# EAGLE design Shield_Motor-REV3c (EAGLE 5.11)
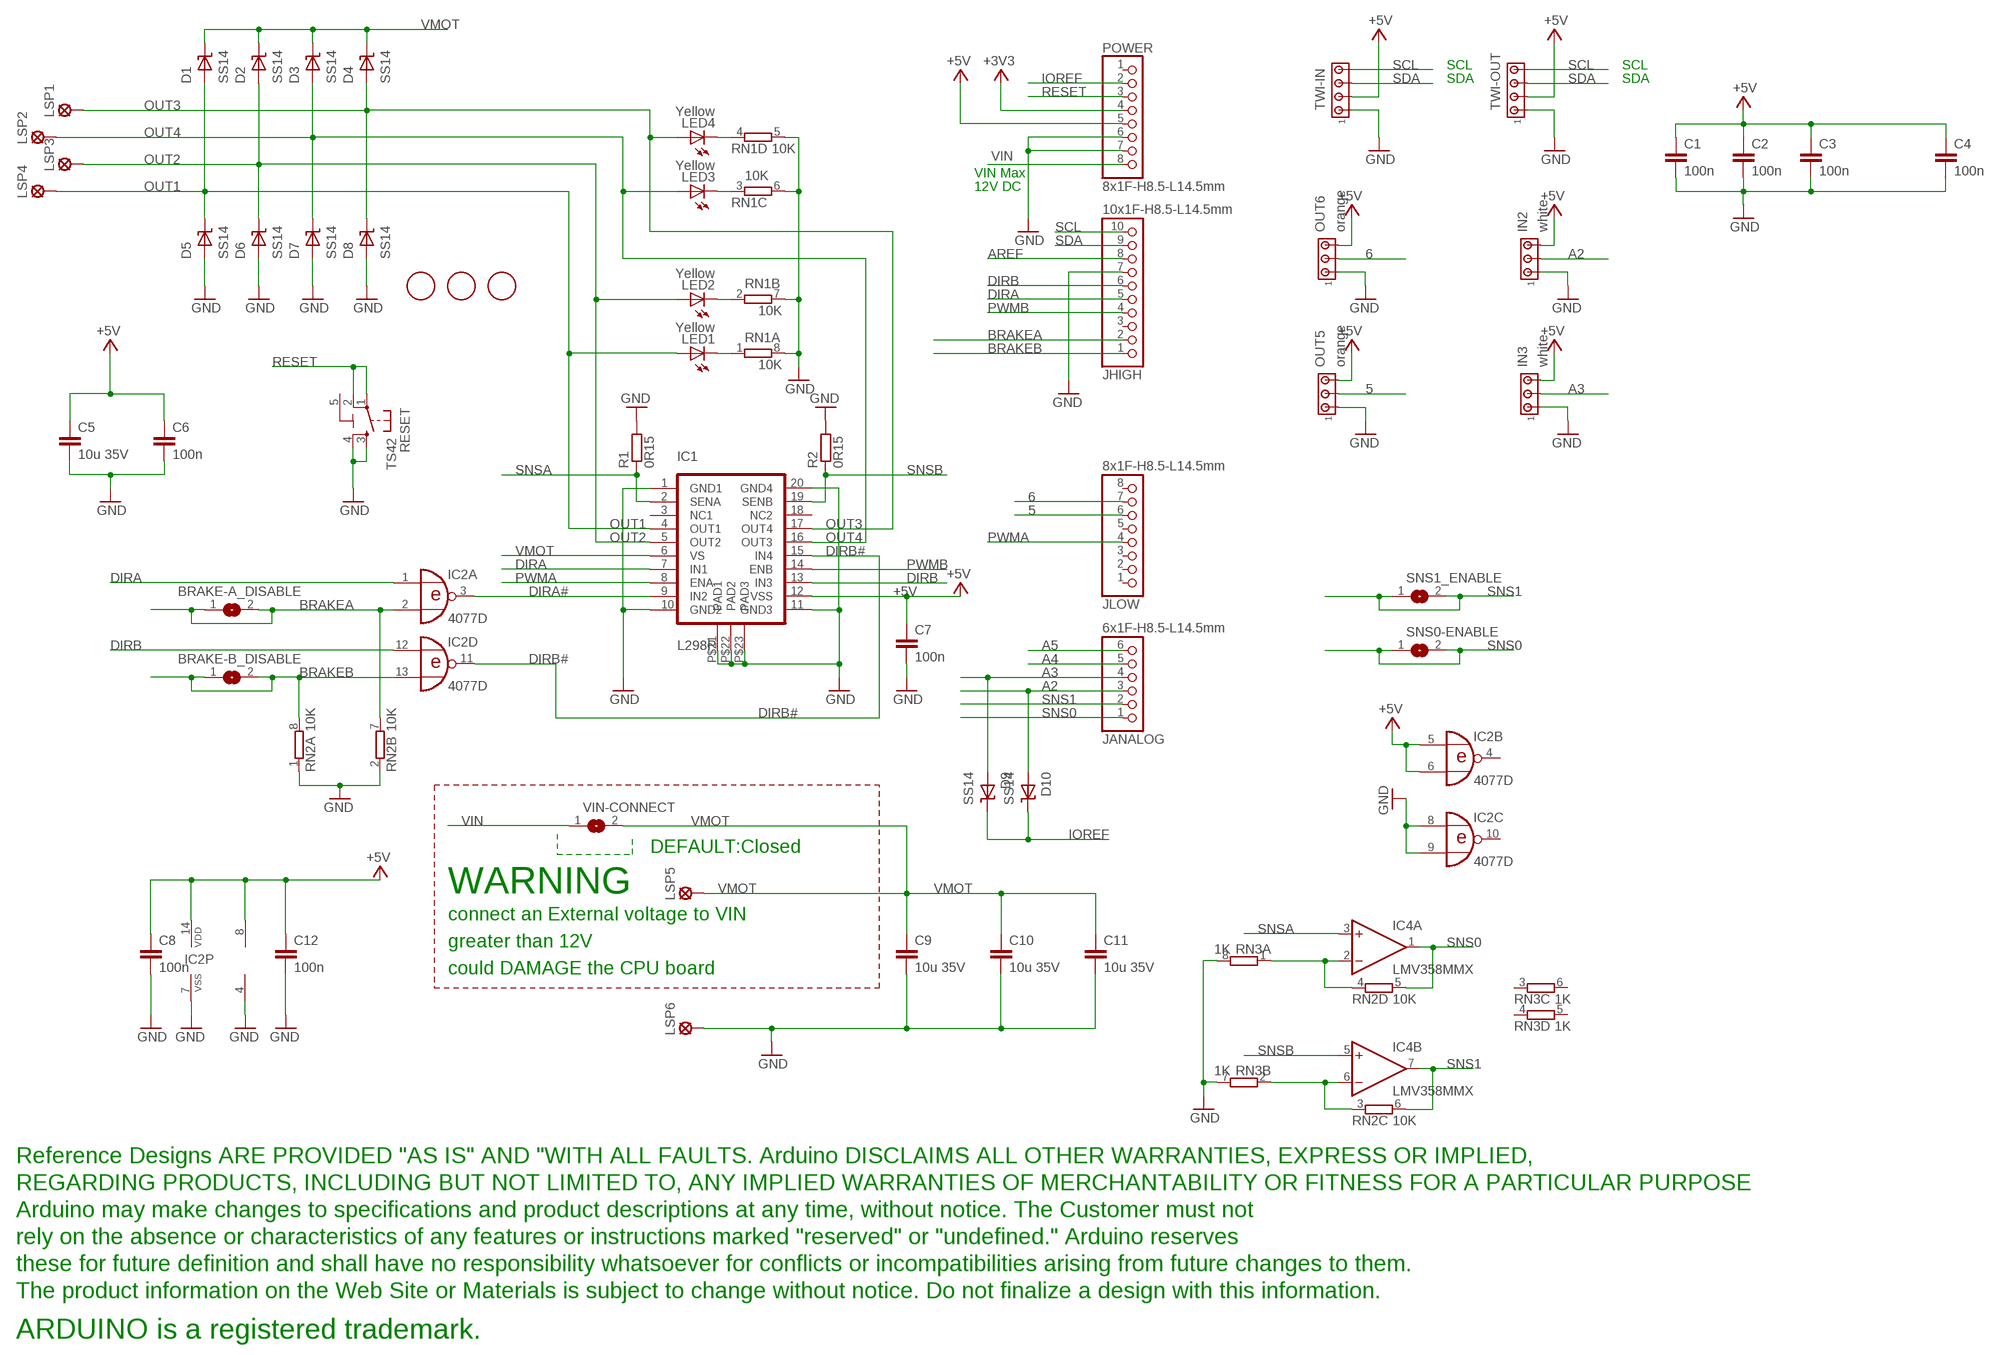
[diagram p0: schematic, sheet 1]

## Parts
BRAKE-A_DISABLE  SJ  [SJ]
BRAKE-B_DISABLE  SJ  [SJ]
C1  100n  C-EUC0603  [C0603-ROUND]
C2  100n  C-EUC0603  [C0603-ROUND]
C3  100n  C-EUC0603  [C0603-ROUND]
C4  100n  C-EUC0603  [C0603-ROUND]
C5  10u 35V  C-EUC1210  [C1210]
C6  100n  C-EUC0603  [C0603-ROUND]
C7  100n  C-EUC0603  [C0603-ROUND]
C8  100n  C-EUC0603  [C0603-ROUND]
C9  10u 35V  C-EUC1210  [C1210]
C10  10u 35V  C-EUC1210  [C1210]
C11  10u 35V  C-EUC1210  [C1210]
C12  100n  C-EUC0603  [C0603-ROUND]
D1  SS14  [SMA]
D2  SS14  [SMA]
D3  SS14  [SMA]
D4  SS14  [SMA]
D5  SS14  [SMA]
D6  SS14  [SMA]
D7  SS14  [SMA]
D8  SS14  [SMA]
D9  SS14  [SMA]
D10  SS14  [SMA]
FID1  FIDUCIALMOUNT  [FIDUCIA-MOUNT]
FID2  FIDUCIALMOUNT  [FIDUCIA-MOUNT]
FID3  FIDUCIALMOUNT  [FIDUCIA-MOUNT]
IC1  L298P  [POWER-SO20]
IC2  4077D  [SO14]
IC4  LMV358MMX  [MSOP08]
IN2  white  MTA03-100  [10X03MTA]
IN3  white  MTA03-100  [10X03MTA]
JANALOG  6x1F-H8.5-L14.5mm  PINHD-1X6TH  [1X06-TH]
JHIGH  10x1F-H8.5-L14.5mm  PINHD-1X10TH  [1X10-TH]
JLOW  8x1F-H8.5-L14.5mm  PINHD-1X8TH  [1X08-TH]
LED1  Yellow  LEDCHIPLED_0805  [CHIPLED_0805]
LED2  Yellow  LEDCHIPLED_0805  [CHIPLED_0805]
LED3  Yellow  LEDCHIPLED_0805  [CHIPLED_0805]
LED4  Yellow  LEDCHIPLED_0805  [CHIPLED_0805]
LSP1  LSP13  [LSP13]
LSP2  LSP13  [LSP13]
LSP3  LSP13  [LSP13]
LSP4  LSP13  [LSP13]
LSP5  LSP13  [LSP13]
LSP6  LSP13  [LSP13]
OUT5  orange  MTA03-100  [10X03MTA]
OUT6  orange  MTA03-100  [10X03MTA]
POWER  8x1F-H8.5-L14.5mm  PINHD-1X8TH  [1X08-TH]
R1  0R15  R-EU_R1206  [R1206]
R2  0R15  R-EU_R1206  [R1206]
RESET  TS42  [TS42]
RN1  10K  4R-NCAY16  [CAY16]
RN2  10K  4R-NCAY16  [CAY16]
RN3  1K  4R-NCAY16  [CAY16]
SNS0-ENABLE  SJ  [SJ]
SNS1_ENABLE  SJ  [SJ]
TWI-IN  MTA04-100  [10X04MTA]
TWI-OUT  MTA04-100  [10X04MTA]
U$1  DISCLAIMER  [DISCLAIMER]
VIN-CONNECT  SJ  [SJ]

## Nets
5: JLOW.6 OUT5.2
6: JLOW.7 OUT6.2
+3V3 [power]: POWER.4
+5V [power]: C1.1 C2.1 C3.1 C4.1 C5.1 C6.1 C7.1 C8.1 C12.1 IC1.P$12(VSS) IC2.5(B:I0) IC2.6(B:I1) IC2.14(P:VDD) IC4.8(P:V+) IN2.3 IN3.3 OUT5.3 OUT6.3 POWER.5 TWI-IN.2 TWI-OUT.2
A2: D10.P$2(A) IN2.2 JANALOG.3
A3: D9.P$2(A) IN3.2 JANALOG.4
A4: JANALOG.5
A5: JANALOG.6
AREF: JHIGH.8
BRAKEA: BRAKE-A_DISABLE.1 BRAKE-A_DISABLE.2 IC2.2(A:I1) JHIGH.2 RN2.7
BRAKEB: BRAKE-B_DISABLE.1 BRAKE-B_DISABLE.2 IC2.13(D:I1) JHIGH.1 RN2.8
DIRA: IC1.P$7(IN1) IC2.1(A:I0) JHIGH.5
DIRA#: IC1.P$9(IN2) IC2.3(A:O)
DIRB: IC1.P$13(IN3) IC2.12(D:I0) JHIGH.6
DIRB#: IC1.P$15(IN4) IC2.11(D:O)
GND [power]: C1.2 C2.2 C3.2 C4.2 C5.2 C6.2 C7.2 C8.2 C9.2 C10.2 C11.2 C12.2 D5.P$2(A) D6.P$2(A) D7.P$2(A) D8.P$2(A) IC1.P$1(GND1) IC1.P$10(GND2) IC1.P$11(GND3) IC1.P$20(GND4) IC1.P$21(PAD1) IC1.P$22(PAD2) IC1.P$23(PAD3) IC2.7(P:VSS) IC2.8(C:I0) IC2.9(C:I1) IC4.4(P:V-) IN2.1 IN3.1 JHIGH.7 LSP6.MP OUT5.1 OUT6.1 POWER.6 POWER.7 R1.2 R2.2 RESET.3 RESET.4 RN1.5 RN1.6 RN1.7 RN1.8 RN2.1 RN2.2 RN3.7 RN3.8 TWI-IN.1 TWI-OUT.1
IOREF: D9.P$1(K) D10.P$1(K) POWER.2
N$1: LED4.C RN1.4
N$2: LED3.C RN1.3
N$3: LED2.C RN1.2
N$4: LED1.C RN1.1
N$5: IC4.2(A:-IN) RN2.4 RN3.1
N$7: IC4.6(B:-IN) RN2.3 RN3.2
OUT1: D1.P$2(A) D5.P$1(K) IC1.P$4(OUT1) LED1.A LSP4.MP
OUT2: D2.P$2(A) D6.P$1(K) IC1.P$5(OUT2) LED2.A LSP3.MP
OUT3: D4.P$2(A) D8.P$1(K) IC1.P$17(OUT4) LED4.A LSP1.MP
OUT4: D3.P$2(A) D7.P$1(K) IC1.P$16(OUT3) LED3.A LSP2.MP
PWMA: IC1.P$8(ENA) JLOW.4
PWMB: IC1.P$14(ENB) JHIGH.4
RESET: POWER.3 RESET.1 RESET.2
SCL: JHIGH.10 TWI-IN.4 TWI-OUT.4
SDA: JHIGH.9 TWI-IN.3 TWI-OUT.3
SNS0: IC4.1(A:OUT) JANALOG.1 RN2.5 SNS0-ENABLE.1 SNS0-ENABLE.2
SNS1: IC4.7(B:OUT) JANALOG.2 RN2.6 SNS1_ENABLE.1 SNS1_ENABLE.2
SNSA: IC1.P$2(SENA) IC4.3(A:+IN) R1.1
SNSB: IC1.P$19(SENB) IC4.5(B:+IN) R2.1
VIN [VIN]: POWER.8 VIN-CONNECT.1
VMOT: C9.1 C10.1 C11.1 D1.P$1(K) D2.P$1(K) D3.P$1(K) D4.P$1(K) IC1.P$6(VS) LSP5.MP VIN-CONNECT.2
Unconnected: IC1.P$3(NC1) IC1.P$18(NC2) IC2.4(B:O) IC2.10(C:O) JHIGH.3 JLOW.1 JLOW.2 JLOW.3 JLOW.5 JLOW.8 POWER.1 RN3.3 RN3.4 RN3.5 RN3.6

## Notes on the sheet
- SCL | SCL
- SDA | SDA
- VIN Max
- 12V DC
- DEFAULT:Closed
- WARNING
- connect an External voltage to VIN
- greater than 12V
- could DAMAGE the CPU board

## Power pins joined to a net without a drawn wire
5-GND: RESET.5(5-GND)

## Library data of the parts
BRAKE-A_DISABLE BRAKE-B_DISABLE SNS0-ENABLE SNS1_ENABLE VIN-CONNECT = jumper:SJ: SMD solder JUMPER
C1-C12 = SmartPrj:C-EU: CAPACITOR, European symbol
D1-D10 = SmartPrj:SS14: DIODE SS14 Diode Schottky 1A 40v
FID1-FID3 = SmartPrj:FIDUCIALMOUNT
IC1 = SmartPrj:L298P: L298P DUAL FUL-BRIDGE DRIVER PowerSO20
IC2 = 40xx:4077: Quad XNOR
IC4 = linear:LMV358?*: Dual General Purpose, Low Voltage, Rail-to-Rail Output Operational Amplifiers Source: http://www.national.com/mpf/LM/LMV321.html http://www.national.com/dt/lmv_qual.pdf
IN2 IN3 OUT5 OUT6 = SmartPrj:MTA03-100: PIN HEADER; OC_FARNELL: unknown; OC_NEWARK: unknown
JANALOG = SmartPrj:PINHD-1X6: PIN HEADER
JHIGH = SmartPrj:PINHD-1X10: PIN HEADER
JLOW POWER = SmartPrj:PINHD-1X8: PIN HEADER
LED1-LED4 = led:LED: LED
LSP1-LSP6 = solpad:LSP13: SOLDER PAD
R1 R2 = SmartPrj:R-EU_: RESISTOR, European symbol
RESET = SmartPrj:TS42: TS42 Dongnan Electronics Tact switch VDC 12V - 50mA
RN1-RN3 = resistor-dil:4R-N: Array Chip Resistor Source: RS Component / Phycomp
TWI-IN TWI-OUT = con-amp:MTA04-100: AMP connector
U$1 = SmartPrj:DISCLAIMER

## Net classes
0 default: width 0.406 mm, drill 0.61 mm, clearance 0.152 mm
1 power: width 0.406 mm, drill 0.61 mm, clearance 0.152 mm
2 VIN: width 0.406 mm, drill 0.61 mm, clearance 0.152 mm

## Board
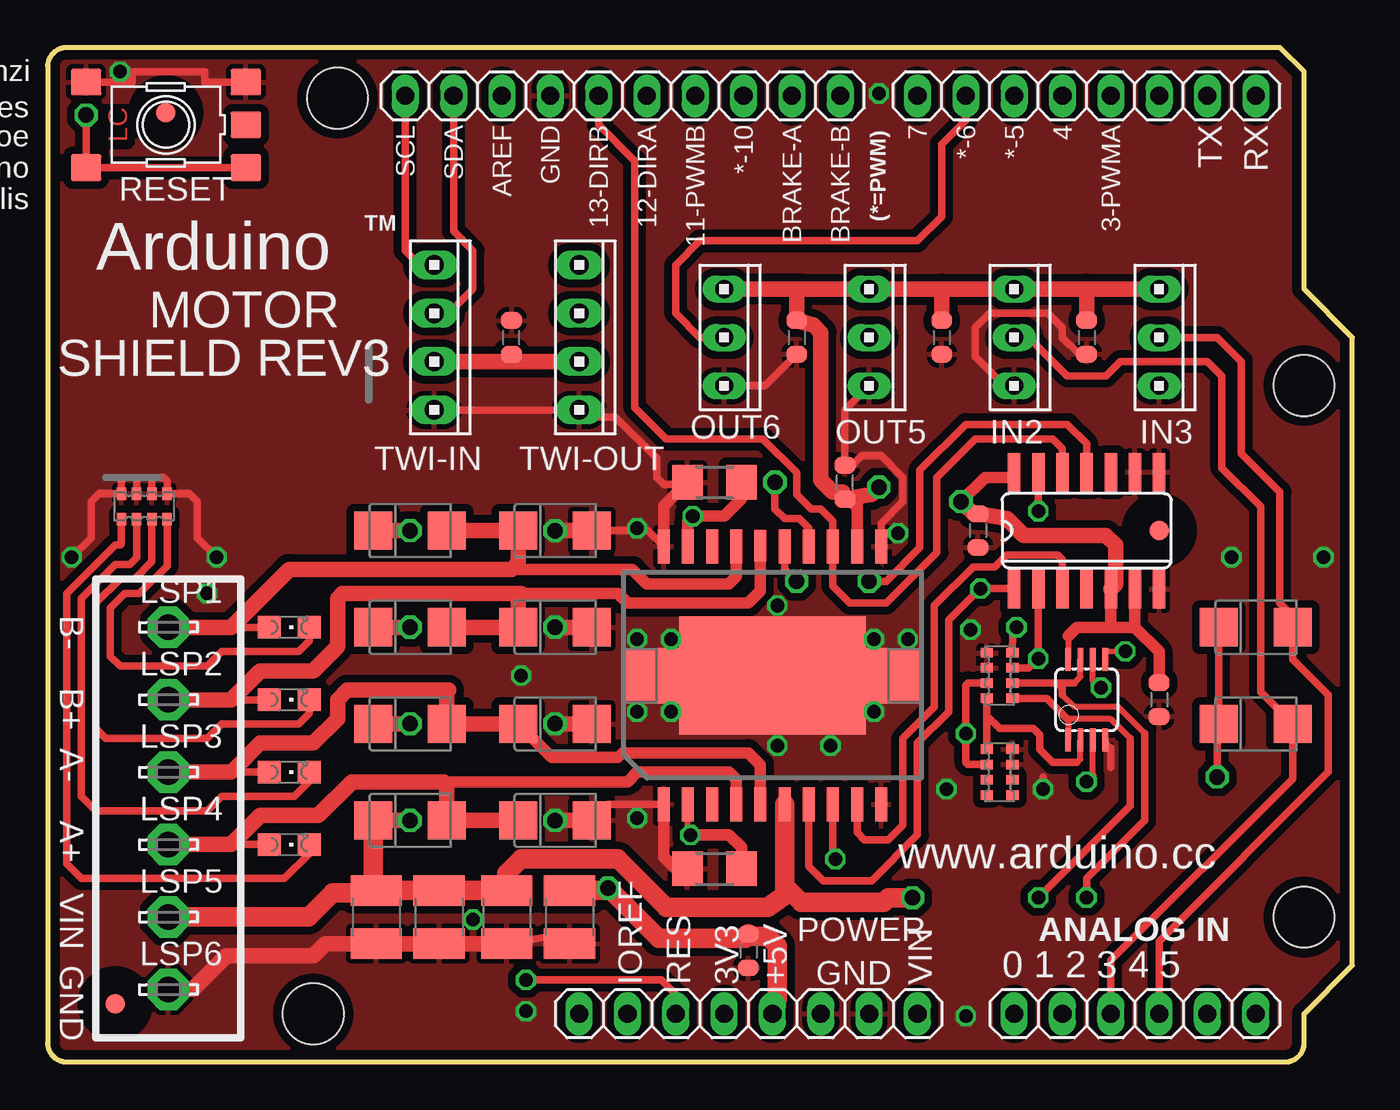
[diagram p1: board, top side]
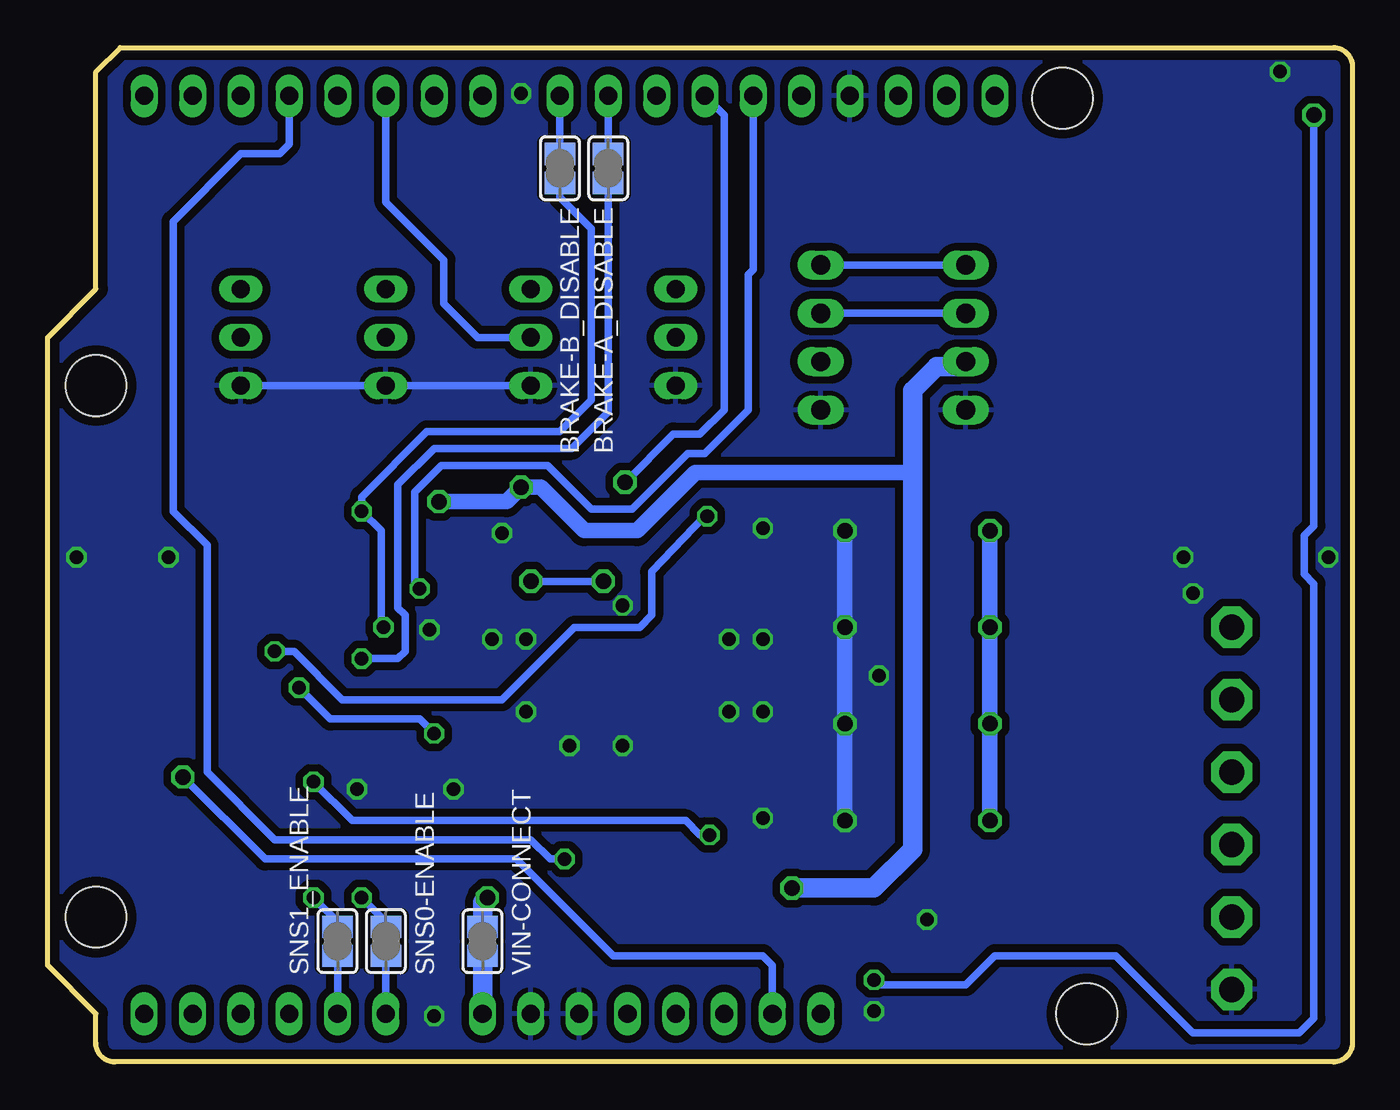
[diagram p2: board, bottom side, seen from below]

Size 68.58 x 53.34 mm. Coordinates in mm from the lower left corner, seen from the top.
Outline: 66.04,2.54 68.58,5.08 68.58,38.1 66.04,40.64 66.04,52.07 64.77,53.34 1,53.34 arc90 0,52.34 0,1 arc90 1,0 65.04,0 arc90 66.04,1 66.04,2.54
Copper layers (1*16): Top 0.035mm / dielectric 1.5mm / Bottom 0.035mm
Design rules "default *": minimum track width 10mil, minimum drill 10mil, track to track 12mil, track to pad 12mil, pad to pad 12mil, via to via 12mil, smd to smd 12mil, copper to edge 20mil, drill to drill 10mil, minimum pad ring 6mil, minimum via ring 6mil, stop-mask expansion 2mil, vias tented up to drill 32mil, thermal gap 10mil
Holes 3.2 mm at 66.04,35.56 66.04,7.62 15.24,50.67 13.97,2.54

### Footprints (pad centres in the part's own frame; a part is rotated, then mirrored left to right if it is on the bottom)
SJ = smd 1.168 x 1.6: 1 -0.762,0; 2 0.762,0
C0603-ROUND = smd 0.898 x 1.1: 1 -0.889,0; 2 0.889,0
C1210 = smd 1.6 x 2.7: 1 -1.4,0; 2 1.4,0
SMA = smd 2 x 2: P$1 -1.94,0; P$2 1.94,0
FIDUCIA-MOUNT = smd 1.016 x 1.016: P$1 0,0
POWER-SO20 = smd 0.635 x 1.778: P$1 -5.715,-6.782; P$2 -4.445,-6.782; P$3 -3.175,-6.782; P$4 -1.905,-6.782; P$5 -0.635,-6.782; P$6 0.635,-6.782; P$7 1.905,-6.782; P$8 3.175,-6.782; P$9 4.445,-6.782; P$10 5.715,-6.782; P$11 5.715,6.782; P$12 4.445,6.782; P$13 3.175,6.782; P$14 1.905,6.782; P$15 0.635,6.782; P$17 -1.905,6.782; P$18 -3.175,6.782; P$19 -4.445,6.782; P$20 -5.715,6.782 | smd 0.635 x 1.651: P$16 -0.635,6.833 | smd 9.804 x 6.198: P$21 0,0 | smd 3.048 x 2.921: P$22 -6.426,0; P$23 6.426,0
SO14 = smd 0.66 x 2.032: 1 -3.81,-3.073; 2 -2.54,-3.073; 3 -1.27,-3.073; 4 0,-3.073; 5 1.27,-3.073; 6 2.54,-3.073; 7 3.81,-3.073; 8 3.81,3.073; 9 2.54,3.073; 10 1.27,3.073; 11 0,3.073; 12 -1.27,3.073; 13 -2.54,3.073; 14 -3.81,3.073
MSOP08 = smd 0.3 x 1.2: 1 -0.976,-2.113; 2 -0.326,-2.113; 3 0.324,-2.113; 4 0.974,-2.113; 5 0.974,2.112; 6 0.324,2.112; 7 -0.326,2.112; 8 -0.976,2.112
10X03MTA = drill 0.95 long: 1 2.54,0; 2 0,0; 3 -2.54,0
1X06-TH = drill 0.95 pad 1.422 long: 1 -6.35,0; 2 -3.81,0; 3 -1.27,0; 4 1.27,0; 5 3.81,0; 6 6.35,0
1X10-TH = drill 0.95 pad 1.422 long: 1 -11.43,0; 2 -8.89,0; 3 -6.35,0; 4 -3.81,0; 5 -1.27,0; 6 1.27,0; 7 3.81,0; 8 6.35,0; 9 8.89,0; 10 11.43,0
1X08-TH = drill 0.95 pad 1.422 long: 1 -8.89,0; 2 -6.35,0; 3 -3.81,0; 4 -1.27,0; 5 1.27,0; 6 3.81,0; 7 6.35,0; 8 8.89,0
CHIPLED_0805 = smd 1.2 x 1.2: A 0,-1.05; C 0,1.05
LSP13 = drill 1.321 pad 2.159 octagon: MP 0,0
R1206 = smd 1.6 x 1.803: 1 -1.422,0; 2 1.422,0
TS42 = smd 1.6 x 1.4: 1 -4.2,2.25; 2 4.2,2.25; 3 -4.2,-2.25; 4 4.2,-2.25; 5 -4.2,0
CAY16 = smd 0.5 x 0.65: 1 -1.2,-0.675; 2 -0.4,-0.675; 3 0.4,-0.675; 4 1.2,-0.675; 5 1.2,0.675; 6 0.4,0.675; 7 -0.4,0.675; 8 -1.2,0.675
10X04MTA = drill 1.016 long: 1 3.81,0; 2 1.27,0; 3 -1.27,0; 4 -3.81,0

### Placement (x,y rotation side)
BRAKE-A_DISABLE  39.12,46.99 270 bottom
BRAKE-B_DISABLE  41.66,46.99 270 bottom
C1  39.37,38.1 270 top
C2  24.38,38.1 90 top
C3  54.61,38.1 270 top
C4  46.99,38.1 270 top
C5  27.43,7.62 270 top
C6  36.83,5.84 270 top
C7  41.91,30.48 90 top
C8  48.9,27.94 270 top
C9  24.13,7.62 270 top
C10  20.57,7.62 270 top
C11  17.27,7.62 270 top
C12  58.42,19.05 270 top
D1  19.05,12.7 0 top
D2  19.05,17.78 0 top
D3  19.05,22.86 0 top
D4  19.05,27.94 0 top
D5  26.67,12.7 0 top
D6  26.67,17.78 0 top
D7  26.67,22.86 0 top
D8  26.67,27.94 0 top
D9  63.5,22.86 0 top
D10  63.5,17.78 0 top
FID1  6.22,49.91 0 top
FID2  3.56,3.05 0 top
FID3  58.42,27.94 0 top
IC1  38.1,20.32 0 top
IC2  54.61,27.94 0 top
IC4  54.61,19.05 0 top
IN2  50.8,38.1 270 top
IN3  58.42,38.1 270 top
JANALOG  57.15,2.54 0 top
JHIGH  30.23,50.8 180 top
JLOW  54.61,50.8 180 top
LED1  12.7,11.43 270 top
LED2  12.7,15.24 270 top
LED3  12.7,19.05 270 top
LED4  12.7,22.86 270 top
LSP1  6.35,22.86 0 top
LSP2  6.35,19.05 0 top
LSP3  6.35,15.24 0 top
LSP4  6.35,11.43 0 top
LSP5  6.35,7.62 0 top
LSP6  6.35,3.81 0 top
OUT5  43.18,38.1 270 top
OUT6  35.56,38.1 270 top
POWER  36.83,2.54 0 top
R1  35.05,10.16 180 top
R2  35.05,30.48 180 top
RESET  6.22,49.28 180 top
RN1  5.08,29.21 0 top
RN2  50.04,20.32 270 top
RN3  50.04,15.24 270 top
SNS0-ENABLE  50.8,6.35 90 bottom
SNS1_ENABLE  53.34,6.35 90 bottom
TWI-IN  20.32,38.1 270 top
TWI-OUT  27.94,38.1 270 top
U$1  not placed on the board
VIN-CONNECT  45.72,6.35 90 bottom

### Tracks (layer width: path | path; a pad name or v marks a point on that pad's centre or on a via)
5
  Bottom 0.406: OUT5.2 45.97,38.1 47.75,39.88 47.75,42.16 50.8,45.21 JLOW.6
6
  Top 0.406: OUT6.2 34.29,38.1 33.02,39.37 33.02,41.91 34.29,43.18 45.72,43.18 46.99,44.45 46.99,48.26 48.26,49.53 JLOW.7
+5V  (via drill 0.81)
  Top 0.305: 53.63,22.39 IC4.8
  Top 0.406: 50.8,30.73 IC2.14 | 24.38,36.83 C2.1
  Top 0.61: 53.63,22.39 54.1,22.86 55.88,22.86 | 55.88,22.86 57.15,22.86 | 57.15,22.86 58.42,21.59 C12.1 | 41.78,29.97 C7.1 42.55,29.2 IC1.P$12 | IC2.5 55.88,22.86 | 57.15,22.86 IC2.6 | 50.8,30.73 49.28,30.73 v48.01,29.46
  Top 0.813: 39.62,40.64 OUT6.3 | 39.62,40.64 OUT5.3 46.99,40.64 | 39.62,40.64 39.37,40.39 C1.1 40.26,38.73 40.64,38.35 40.64,30.61 41.27,29.97 41.78,29.97 | 54.61,40.64 IN2.3 46.99,40.64 | 54.61,40.64 IN3.3 | 54.61,40.64 C3.1 | v48.01,29.46 48.64,28.83 C8.1 50.42,28.57 51.31,27.69 55.63,27.69 56.13,27.18 56.13,25.12 IC2.5 | 46.99,40.64 C4.1 | TWI-IN.2 24.38,36.83 TWI-OUT.2 | C7.1 43.29,29.83 v43.69,30.23
  Top 1.016: POWER.5 38.1,3.05 38.35,3.3 38.35,6.1 37.85,6.6 36.96,6.6 C6.1 36.7,6.6 36.7,6.49 32.12,6.49 v29.46,9.14 29.59,9.02 C5.1
  Bottom 0.813: v48.01,29.46 44.45,29.46 v43.69,30.23 42.67,30.23 40.39,27.94 37.59,27.94 34.54,30.99 23.11,30.99
  Bottom 1.016: v29.46,9.14 25.15,9.14 23.11,11.18 23.11,30.99 23.11,35.31 21.84,36.58 20.57,36.58 TWI-IN.2
A2
  Top 0.406: IN2.2 51.56,38.1 53.59,36.07 55.63,36.07 56.39,36.83 60.96,36.83 61.72,36.07 61.72,31.24 63.75,29.21 63.75,19.47 D10.P$2 65.44,14.89 55.88,5.33 JANALOG.3
A3
  Top 0.406: IN3.2 61.47,38.1 62.74,36.83 62.74,32 64.77,29.97 64.77,24.13 65.53,23.37 65.53,22.95 D9.P$2 65.44,21.17 67.31,19.3 67.31,15.24 58.42,6.35 JANALOG.4
BRAKEA  (via drill 0.71)
  Top 0.406: RN2.7 51.58,20.72 v52.07,21.21 IC2.2
  Bottom 0.406: v52.07,21.21 50.16,21.21 49.78,21.59 49.78,23.5 50.16,23.88 50.16,30.35 48.26,32.26 41.02,32.26 39.12,34.16 BRAKE-A_DISABLE.2 BRAKE-A_DISABLE.1 JHIGH.2
BRAKEB  (via drill 0.71)
  Top 0.406: RN2.8 50.73,22.54 v50.93,22.86 | v52.07,28.96 IC2.13
  Bottom 0.406: v50.93,22.86 51.05,22.99 51.05,27.94 v52.07,28.96 52.07,29.72 48.64,33.15 41.66,33.15 40.01,34.8 40.01,43.81 41.66,45.47 BRAKE-B_DISABLE.2 BRAKE-B_DISABLE.1 JHIGH.1
DIRA  (via drill 0.71)
  Top 0.305: 50.77,24.89 IC2.1
  Top 0.406: 50.77,24.89 v49.02,24.89 47.37,23.24 47.37,18.41 45.72,16.76 45.72,11.94 43.31,9.53 40.77,9.53 40.01,10.29 IC1.P$7
  Bottom 0.406: v49.02,24.89 49.28,25.15 49.28,29.97 47.88,31.37 42.29,31.37 40.01,29.08 37.85,29.08 34.92,32 34.04,32 31.75,34.29 31.75,41.4 31.5,41.66 JHIGH.5
DIRA#
  Top 0.406: IC2.3 53.34,26.42 53.09,26.67 50.42,26.67 49.78,26.04 48.64,26.04 46.61,24 46.61,18.67 44.96,17.02 44.96,12.45 44.2,11.68 42.93,11.68 42.55,12.06 IC1.P$9
DIRB
  Top 0.406: IC2.12 53.34,32.26 52.83,32.77 48.77,32.77 46.74,30.73 46.74,26.8 44.07,24.13 42.16,24.13 41.27,25.02 IC1.P$13 41.27,28.45 40.64,29.08 40.13,29.08 39.37,29.84 39.37,30.99 37.59,32.77 32.51,32.77 30.86,34.42 30.86,47.37 28.96,49.28 JHIGH.6
DIRB#  (via drill 0.81)
  Top 0.406: IC2.11 54.61,32.51 53.59,33.53 48.26,33.53 45.85,31.11 45.85,27.05 44.07,25.27 v43.18,25.27 | v39.37,25.27 38.73,25.91 IC1.P$15
  Bottom 0.406: v39.37,25.27 v43.18,25.27
GND  (via drill 0.71, 0.81)
  Top 0.305: IC4.4 55.58,16.81 55.88,16.51
  Top 0.406: RESET.4 4.45,51.53 4.45,52.07 8.26,52.07 8.26,51.53 RESET.3 | OUT6.1 37.72,35.56 C1.2 | OUT5.1 41.91,34.29 C7.2 42.05,31.13 42.8,31.88 43.81,31.88 44.96,30.73 44.96,29.46 43.81,28.32 IC1.P$11 | C3.2 54.23,37.21 53.34,38.1 53.34,38.61 52.58,39.37 49.53,39.37 48.77,38.61 48.77,37.08 50.29,35.56 IN2.1 | D8.P$2 31.55,27.94 IC1.P$20 | C9.2 27.18,6.73 | IC1.P$1 29.45,13.54 D5.P$2 | R2.2 33.5,30.35 32.38,30.35 32,30.73 32,31.75 29.84,33.91 28.32,33.91 TWI-OUT.1 TWI-IN.1 | 4.57,30.73 4.06,30.73 3.88,30.55 RN1.8 2.71,29.89 2.29,29.46 2.29,27.56 v1.27,26.54 | 4.57,30.73 5.33,30.73 | 5.33,30.73 6.1,30.73 6.28,30.55 RN1.5 7.45,29.89 7.87,29.46 7.87,27.56 v8.89,26.54 | RN1.7 4.68,30.63 4.57,30.73 | RN1.6 5.48,30.59 5.33,30.73 | v48.51,22.73 48.64,22.99 | v52.32,14.35 52.32,14.99 | 55.88,16.51 55.88,15.49
  Top 0.61: IC1.P$1 32.38,10.79 33.02,10.16 R1.2 | IC1.P$20 32.38,29.23 R2.2
  Top 0.813: v26.67,27.94 D8.P$2 | v26.67,12.7 D5.P$2 | v26.67,17.78 D6.P$2 | v26.67,22.86 D7.P$2 | LSP6.MP 7.62,3.81 9.4,5.59 13.97,5.59 14.6,6.22 C11.2 C10.2 C9.2
  Bottom 0.406: OUT5.1 IN2.1 IN3.1
  Bottom 0.813: v26.67,27.94 v26.67,22.86 v26.67,17.78 v26.67,12.7
  other vias: 43.69,50.93 48.26,2.41 67.06,26.54 25.15,2.67 43.43,22.23 32.77,22.23 43.43,18.41 32.77,18.41 38.35,24 38.35,16.64 47.24,14.35 30.99,12.83 30.99,28.07 24.89,20.32 8.38,24.64 3.81,52.07 62.23,26.54 22.35,7.49 30.99,22.23 30.99,18.41 45.21,22.23 41.15,16.64 44.7,27.81
  pour Bottom (isolate 0.406): -2.54,55.88 71.12,55.88 71.12,-2.54 -2.54,-2.54
  pour Top (isolate 0.406): -5.08,53.34 68.58,53.34 68.58,0 -5.08,0
IOREF  (via drill 0.81)
  Top 0.406: v61.47,14.99 61.47,17.69 D10.P$1 D9.P$1
  Bottom 0.406: POWER.2 30.48,5.08 30.99,5.59 38.86,5.59 43.94,10.67 57.15,10.67 v61.47,14.99
N$1
  Top 0.406: LED4.C 13.75,22.13 13.21,21.59 9.14,21.59 8.38,20.83 3.81,20.83 3.3,21.34 3.3,23.88 4.06,24.64 4.83,24.64 6.28,26.09 RN1.4
N$2
  Top 0.406: LED3.C 13.75,18.32 13.21,17.78 9.14,17.78 8.38,17.02 3.05,17.02 2.54,17.53 2.54,24.13 3.81,25.4 4.57,25.4 5.48,26.31 RN1.3
N$3
  Top 0.406: LED2.C 13.75,14.77 12.95,13.97 9.14,13.97 8.38,13.21 2.54,13.21 1.78,13.97 1.78,24.38 3.56,26.16 4.32,26.16 4.68,26.52 RN1.2
N$4
  Top 0.406: LED1.C 13.75,10.96 12.45,9.65 1.78,9.65 1.02,10.41 1.02,24.64 3.56,27.18 3.81,27.18 3.88,27.25 RN1.1
N$5
  Top 0.305: IC4.2 54.28,15.93 54.1,15.75
  Top 0.406: 49.36,18.2 49.36,18.29 RN2.4 | 54.1,15.75 52.83,15.75 52.14,16.44 52.14,17.2 51.82,17.53 50.04,17.53 49.36,18.2 | RN3.1 49.36,18.2
N$7  (via drill 0.71)
  Top 0.305: 49.38,19.94 RN2.3 | IC4.6 54.93,20.01 v55.37,19.68
  Top 0.406: RN3.2 48.37,15.64 48.26,15.75 v48.26,17.27 48.26,19.81 48.39,19.94 49.38,19.94
  Bottom 0.406: v55.37,19.68 53.72,18.03 49.02,18.03 v48.26,17.27
OUT1
  Top 0.406: 9.4,11.43 LED1.A
  Top 0.61: IC1.P$4 36.2,14.86 35.81,15.24 30.99,15.24 30.48,14.73 20.83,14.73
  Top 0.813: LSP4.MP 9.4,11.43 9.65,11.43 11.18,12.95 14.22,12.95 16,14.73 20.83,14.73 20.99,14.57 D1.P$2 D5.P$1
OUT2
  Top 0.406: LED2.A 10.16,15.24 9.91,15.49
  Top 0.61: IC1.P$5 37.47,15.62 36.83,16.26 30.23,16.26 29.97,16 26.51,16 D6.P$1
  Top 0.813: LSP3.MP 9.65,15.24 9.91,15.49 11.18,16.76 13.97,16.76 15.24,18.03 15.24,19.05 15.75,19.56 21.08,19.56 20.99,19.47 D2.P$2 D6.P$1
OUT3
  Top 0.406: 9.4,22.86 LED4.A
  Top 0.61: IC1.P$17 36.2,25.53 35.81,25.15 31.5,25.15 30.73,25.91 24.38,25.91
  Top 0.813: LSP1.MP 9.4,22.86 9.65,22.86 12.7,25.91 24.38,25.91 24.73,26.25 D8.P$1 D4.P$2
OUT4
  Top 0.406: 9.65,19.05 LED3.A
  Top 0.61: 24.89,24.64 29.97,24.64 30.48,24.13 36.83,24.13 37.47,24.77 IC1.P$16
  Top 0.813: LSP2.MP 9.65,19.05 11.18,20.57 13.97,20.57 15.24,21.84 15.24,24.38 15.49,24.64 24.89,24.64 24.73,24.48 D7.P$1 | D7.P$1 D3.P$2 | D7.P$1 25.15,22.86
PWMA  (via drill 0.71)
  Top 0.406: IC1.P$8 41.27,10.79 v41.4,10.67
  Bottom 0.406: v41.4,10.67 42.16,10.67 43.18,11.68 56.64,11.68 60.2,15.24 60.2,27.18 61.98,28.96 61.98,44.2 58.42,47.75 56.39,47.75 55.88,48.26 JLOW.4
PWMB  (via drill 0.81)
  Top 0.406: IC1.P$14 40.01,28.07 39.5,28.57 38.73,28.57 38.23,29.08 38.23,30.35 v38.23,30.48
  Bottom 0.406: v38.23,30.48 35.69,33.02 34.29,33.02 33.02,34.29 33.02,49.78 JHIGH.4
RESET  (via drill 0.71, 0.81)
  Top 0.305: v2.03,49.78 v2.02,49.77
  Top 0.406: v2.02,49.77 RESET.2 RESET.1 | v25.15,4.32 32.26,4.32 33.02,3.56 POWER.3
  Bottom 0.406: v2.03,49.78 2.03,28.19 2.54,27.69 2.54,25.65 2.03,25.15 2.03,2.29 2.79,1.52 8.38,1.52 12.45,5.59 18.8,5.59 20.32,4.06 24.89,4.06 v25.15,4.32
SCL
  Top 0.406: JHIGH.10 18.8,42.67 19.56,41.91 TWI-IN.4
  Bottom 0.406: TWI-IN.4 TWI-OUT.4
SDA
  Top 0.406: JHIGH.9 21.34,43.69 22.35,42.67 22.35,40.64 21.08,39.37 TWI-IN.3
  Bottom 0.406: TWI-IN.3 TWI-OUT.3
SNS0  (via drill 0.71)
  Top 0.305: IC4.1 53.63,17.99 53.67,18.03 55.88,18.03 56.9,17.02
  Top 0.406: RN2.5 52.51,19.12 53.63,17.99 | v52.07,8.64 56.9,13.46 56.9,17.02
  Bottom 0.406: JANALOG.1 SNS0-ENABLE.1 SNS0-ENABLE.2 50.8,7.37 v52.07,8.64
SNS1  (via drill 0.71)
  Top 0.305: IC4.7 54.28,20.25 53.96,19.92 | 57.66,17.27 56.26,18.67 53.98,18.67 53.34,19.3
  Top 0.406: 53.09,19.92 RN2.6 | 53.09,19.92 53.96,19.92 | v54.61,8.64 54.61,9.65 57.66,12.7 57.66,17.27 | 53.34,19.3 53.34,19.67 53.09,19.92
  Bottom 0.406: JANALOG.2 SNS1_ENABLE.1 SNS1_ENABLE.2 53.34,7.37 v54.61,8.64
SNSA  (via drill 0.71)
  Top 0.305: IC1.P$2 33.66,12.06 v33.78,11.94 | 54.93,15.06 IC4.3
  Top 0.406: v54.61,14.73 54.93,15.06
  Top 0.61: R1.1 36.47,11.28 35.81,11.94 v33.78,11.94
  Bottom 0.406: v33.78,11.94 34.29,11.94 35.05,12.7 52.58,12.7 v54.61,14.73
SNSB  (via drill 0.71)
  Top 0.305: IC4.5 55.58,21.55 v56.64,21.59
  Top 0.61: IC1.P$19 33.66,28.45 v33.91,28.7 35.56,28.7 36.47,29.62 R2.1
  Bottom 0.406: v33.91,28.7 34.04,28.7 36.83,25.78 36.83,23.5 37.47,22.86 40.89,22.86 44.7,19.05 53.09,19.05 55.63,21.59 v56.64,21.59
VIN
  Bottom 1.016: POWER.8 VIN-CONNECT.1
VMOT  (via drill 0.81)
  Top 0.813: v19.05,27.94 D4.P$1 | D1.P$1 v19.05,12.7 | v19.05,17.78 D2.P$1 | v19.05,22.86 D3.P$1
  Top 1.016: LSP5.MP 13.72,7.62 14.99,8.89 17.14,8.89 C11.1 | 38.73,9.14 38.73,8.76 37.85,8.13 32.51,8.13 29.97,10.67 24.89,10.67 24.13,9.91 C9.1 C10.1 C11.1 | 38.73,9.14 IC1.P$6 | 38.73,9.14 38.86,9.14 39.62,8.38 43.94,8.38 44.2,8.64 v45.47,8.64 | D1.P$1 17.11,9.18 C11.1
  Bottom 0.61: VIN-CONNECT.2 45.72,5.59
  Bottom 0.813: v19.05,12.7 v19.05,17.78 v19.05,22.86 v19.05,27.94
  Bottom 1.016: v45.47,8.64 45.72,8.38 VIN-CONNECT.2

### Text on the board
Top: LC
tPlace: B- | B+ | A- | A+ | VIN | GND
tNames: M.Banzi | D.Cuartielles | T.Igoe | SCL | SDA | AREF | GND | 13-DIRB | 12-DIRA | 11-PWMB | *-10 | BRAKE-A | BRAKE-B | 7 | *-6 | *-5 | 4 | 3-PWMA | TX | RX | G.Martino | D.Mellis | TM | (*=PWM) | Arduino | MOTOR | SHIELD REV3 | www.arduino.cc | ANALOG IN | IOREF | RES | 3V3 | +5V | GND | VIN | 0 1 2 3 4 5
